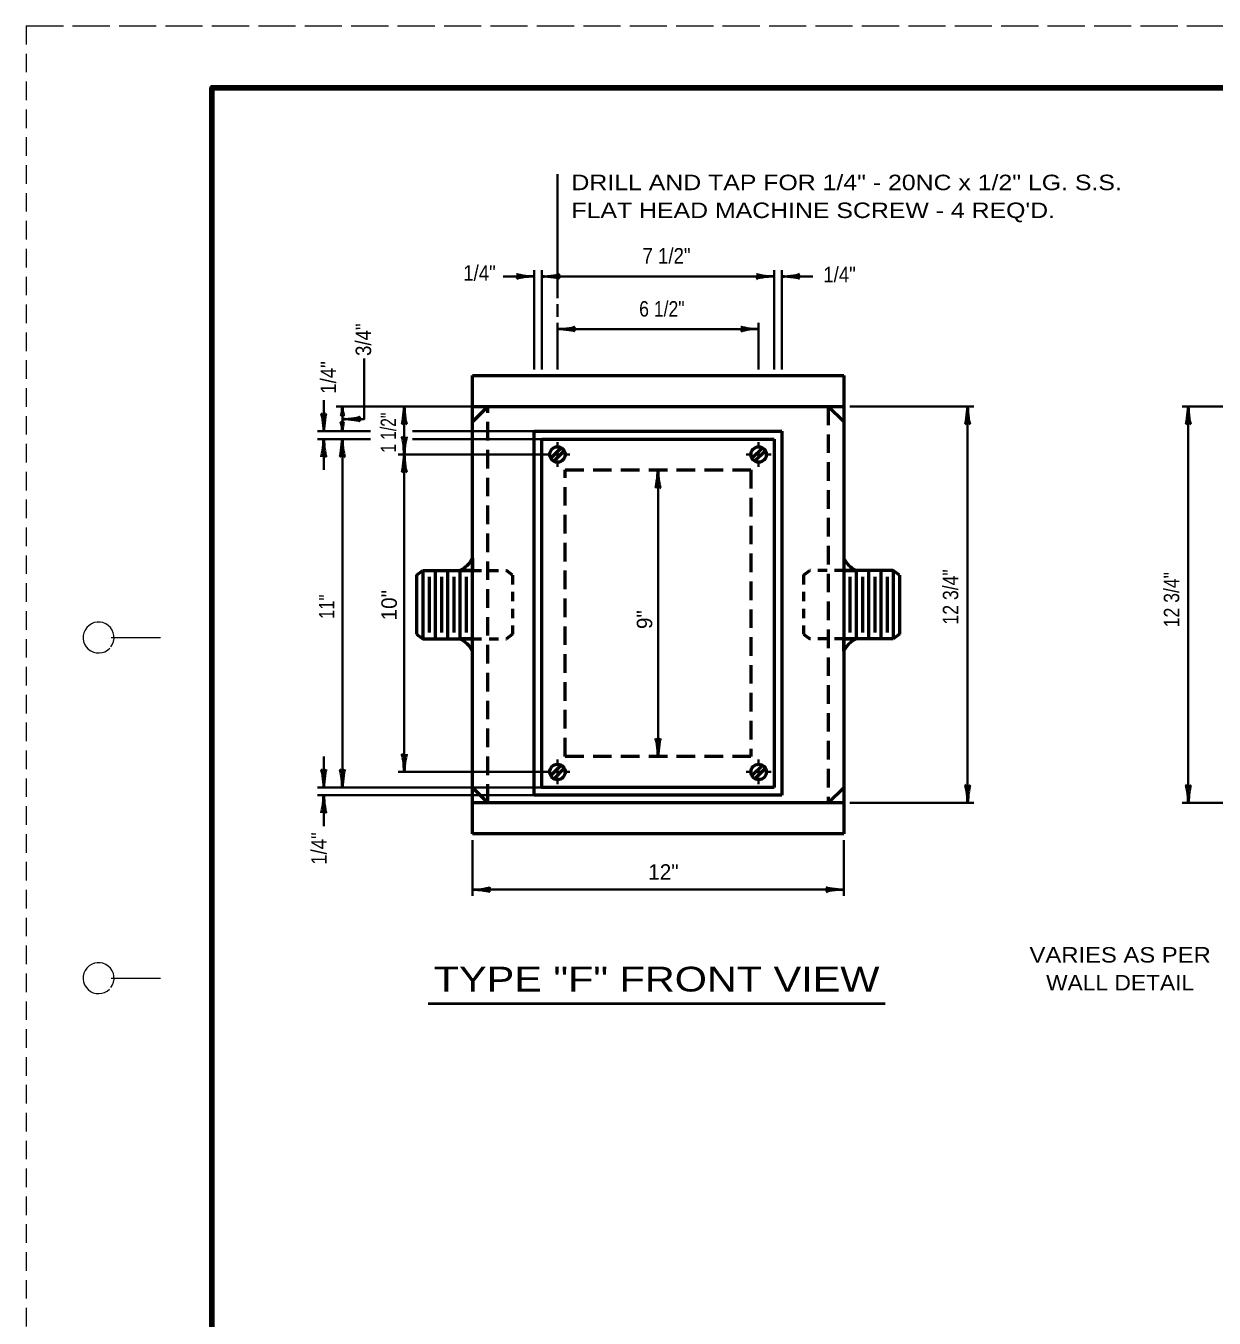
# Model space of a CAD drawing. Extents: x -1 to 679, y 0 to 440.
# Drawn here: x -1.4 to 190.5, y 231 to 439.6 of the extents above; entities that cross this region are included whole.
import ezdxf
from ezdxf.enums import TextEntityAlignment as Align

# ---------------------------------------------------------------- set-up
doc = ezdxf.new("R2010")
doc.units = 0
for name, pattern in [('LONG_DASHED', [7.5, 6, -1.5]), ('MEDIUM_DASHED', [4.5, 3, -1.5]), ('SHORT_DASHED', [2.7, 1.5, -1.2])]:
    doc.linetypes.add(name, pattern=pattern)
doc.layers.add('1', color=7, linetype='Continuous', lineweight=53)
doc.layers.add('61', color=7, linetype='Continuous', lineweight=35)

msp = doc.modelspace()

# ---------------------------------------------------------------- linework, layer by layer
at = {"layer": '1', "linetype": 'MEDIUM_DASHED', "lineweight": 13}
msp.add_line((-1.376, 439.629), (-1.436, -0.411), dxfattribs=at)
at = {"layer": '1', "lineweight": 35}
for p, q in [((84.441, 395.671), (84.441, 415.671)), ((80.691, 399.171), (75.691, 399.171)), ((80.691, 384.171), (80.691, 400.171)), ((81.941, 384.171), (81.941, 400.171)), ((81.941, 399.171), (119.441, 399.171)), ((119.441, 384.171), (119.441, 400.171)), ((120.691, 384.171), (120.691, 400.171)), ((120.691, 399.171), (125.691, 399.171)), ((84.441, 392.671), (84.441, 394.671)), ((84.441, 384.171), (84.441, 391.671)), ((84.441, 390.671), (116.941, 390.671)), ((116.941, 384.171), (116.941, 391.671)), ((46.691, 379.171), (46.691, 374.171)), ((70.691, 378.171), (48.691, 378.171)), ((49.691, 378.171), (49.691, 374.171)), ((131.691, 378.171), (151.691, 378.171)), ((150.691, 378.171), (150.691, 314.171)), ((206.337, 378.171), (185.337, 378.171)), ((186.337, 378.171), (186.337, 314.171)), ((54.251, 374.171), (45.691, 374.171)), ((80.691, 374.171), (61.002, 374.171)), ((54.251, 372.921), (45.691, 372.921)), ((46.691, 372.921), (46.691, 367.921)), ((49.691, 372.921), (49.691, 316.671)), ((81.941, 372.921), (61.002, 372.921)), ((84.441, 371.421), (84.441, 372.421)), ((116.941, 371.421), (116.941, 372.421)), ((82.441, 370.421), (58.691, 370.421)), ((83.441, 370.421), (82.441, 370.421)), ((83.941, 370.421), (84.941, 370.421)), ((84.441, 369.921), (84.441, 370.921)), ((84.441, 369.421), (84.441, 368.421)), ((85.441, 370.421), (86.441, 370.421)), ((115.941, 370.421), (114.941, 370.421)), ((116.441, 370.421), (117.441, 370.421)), ((116.941, 370.921), (116.941, 369.921)), ((116.941, 369.421), (116.941, 368.421)), ((117.941, 370.421), (118.941, 370.421)), ((100.691, 321.671), (100.691, 367.921)), ((46.691, 321.671), (46.691, 316.671)), ((84.441, 320.171), (84.441, 321.171)), ((84.441, 318.671), (84.441, 319.671)), ((116.941, 320.171), (116.941, 321.171)), ((116.941, 319.671), (116.941, 318.671)), ((82.441, 319.171), (58.691, 319.171)), ((83.441, 319.171), (82.441, 319.171)), ((84.941, 319.171), (83.941, 319.171)), ((84.441, 318.171), (84.441, 317.171)), ((85.441, 319.171), (86.441, 319.171)), ((115.941, 319.171), (114.941, 319.171)), ((116.441, 319.171), (117.441, 319.171)), ((116.941, 318.171), (116.941, 317.171)), ((117.941, 319.171), (118.941, 319.171)), ((81.941, 316.671), (45.691, 316.671)), ((80.691, 315.421), (45.691, 315.421)), ((46.691, 315.421), (46.691, 310.421)), ((131.691, 314.171), (151.691, 314.171)), ((207.337, 314.171), (185.337, 314.171)), ((70.691, 308.171), (70.691, 299.171)), ((130.691, 308.171), (130.691, 299.171)), ((70.691, 300.171), (130.691, 300.171))]:
    msp.add_line(p, q, dxfattribs=at)
at = {"layer": '1'}
for p, q in [((70.691, 383.171), (130.691, 383.171)), ((70.691, 378.171), (70.691, 383.171)), ((130.691, 383.171), (130.691, 378.171)), ((70.691, 378.171), (130.691, 378.171)), ((70.691, 351.676), (70.691, 378.171)), ((80.691, 315.421), (80.691, 374.171)), ((80.691, 374.171), (120.691, 374.171)), ((120.691, 374.171), (120.691, 315.421)), ((81.941, 372.921), (119.441, 372.921)), ((83.343, 369.823), (85.039, 371.519)), ((115.843, 369.823), (117.539, 371.519)), ((119.441, 372.921), (119.441, 316.671)), ((85.539, 371.019), (83.843, 369.323)), ((118.039, 371.019), (116.343, 369.323)), ((61.691, 350.921), (62.691, 351.671)), ((61.691, 350.921), (61.691, 341.421)), ((62.691, 351.671), (70.671, 351.671)), ((62.691, 351.671), (62.691, 340.671)), ((63.691, 350.671), (63.691, 341.671)), ((64.691, 351.671), (64.691, 340.671)), ((65.691, 350.671), (65.691, 341.671)), ((66.691, 351.671), (66.691, 340.671)), ((67.691, 350.671), (67.691, 341.671)), ((68.691, 351.671), (68.691, 340.671)), ((69.691, 350.671), (69.691, 341.671)), ((70.691, 316.671), (70.691, 351.671)), ((138.691, 351.671), (130.691, 351.671)), ((131.691, 350.671), (131.691, 341.671)), ((132.691, 351.671), (132.691, 340.671)), ((133.691, 350.671), (133.691, 341.671)), ((134.691, 351.671), (134.691, 340.671)), ((135.691, 350.671), (135.691, 341.671)), ((136.691, 351.671), (136.691, 340.671)), ((137.691, 350.671), (137.691, 341.671)), ((138.691, 351.671), (138.691, 340.671)), ((139.691, 350.921), (138.691, 351.671)), ((139.691, 350.921), (139.691, 341.421)), ((61.691, 341.421), (62.691, 340.671)), ((62.691, 340.671), (70.691, 340.671)), ((138.691, 340.671), (130.691, 340.671)), ((139.691, 341.421), (138.691, 340.671)), ((83.343, 318.573), (85.039, 320.269)), ((85.539, 319.769), (83.843, 318.073)), ((115.843, 318.573), (117.539, 320.269)), ((116.343, 318.073), (118.039, 319.769)), ((70.691, 309.171), (70.691, 316.671)), ((120.691, 315.421), (80.691, 315.421)), ((130.691, 314.171), (70.691, 314.171)), ((130.691, 309.171), (70.691, 309.171))]:
    msp.add_line(p, q, dxfattribs=at)
at = {"layer": '1', "linetype": 'MEDIUM_DASHED'}
for p, q in [((73.191, 314.171), (73.191, 378.171)), ((128.191, 378.171), (128.191, 314.171)), ((85.691, 321.671), (85.691, 367.921)), ((85.691, 367.921), (115.691, 367.921))]:
    msp.add_line(p, q, dxfattribs=at)
at = {"layer": '1', "linetype": 'SHORT_DASHED'}
for p, q in [((70.691, 351.671), (76.191, 351.671)), ((77.191, 350.921), (76.191, 351.671)), ((77.191, 350.921), (77.191, 341.421)), ((124.191, 350.921), (125.191, 351.671)), ((124.191, 350.921), (124.191, 341.421)), ((130.691, 351.671), (125.191, 351.671)), ((70.691, 340.671), (76.191, 340.671)), ((77.191, 341.421), (76.191, 340.671)), ((124.191, 341.421), (125.191, 340.671)), ((130.691, 340.671), (125.191, 340.671))]:
    msp.add_line(p, q, dxfattribs=at)
at = {"layer": '1', "lineweight": 40}
msp.add_line((63.568, 281.786), (137.369, 281.786), dxfattribs=at)
at = {"layer": '1', "lineweight": 35}
for points in [[(49.745, 376.133), (53.232, 376.133), (53.232, 385.936)], [(59.691, 378.171), (59.691, 370.421), (59.691, 319.171)]]:
    msp.add_lwpolyline(points, dxfattribs=at)
at = {"layer": '1'}
for points in [[(70.691, 378.171), (73.191, 378.171), (70.691, 375.671)], [(128.191, 378.171), (130.691, 378.171), (130.691, 375.671)], [(70.691, 314.171), (70.691, 316.671), (73.191, 314.171)], [(130.691, 314.171), (128.191, 314.171), (130.691, 316.671)]]:
    msp.add_lwpolyline(points, close=True, dxfattribs=at)
for points in [[(130.691, 378.171), (130.691, 316.671), (130.691, 309.171)], [(119.441, 316.671), (81.941, 316.671), (81.941, 372.921)], [(70.691, 353.671), (70.691, 351.671), (68.691, 351.671)], [(130.691, 353.671), (130.691, 351.671), (132.691, 351.671)], [(70.691, 338.671), (70.691, 340.671), (68.691, 340.671)], [(130.691, 338.671), (130.691, 340.671), (132.691, 340.671)]]:
    msp.add_lwpolyline(points, dxfattribs=at)
at = {"layer": '1', "linetype": 'MEDIUM_DASHED'}
msp.add_lwpolyline([(115.691, 367.921), (115.691, 321.671), (85.691, 321.671)], dxfattribs=at)
at = {"layer": '1'}
for centre in [(84.441, 370.421), (116.941, 370.421), (84.441, 319.171), (116.941, 319.171)]:
    msp.add_circle(centre, 1.25, dxfattribs=at)
for centre, start, end in [((66.811, 355.552), 295.85509, 334.14491), ((134.572, 355.552), 205.85509, 244.14491), ((66.811, 336.791), 25.85509, 64.14491), ((134.572, 336.791), 115.85509, 154.14491)]:
    msp.add_arc(centre, 4.312, start, end, dxfattribs=at)
at = {"layer": '1', "lineweight": 40}
for centre, major_axis, ratio, start_param, end_param in [((79.6, 398.895), (1.786, 0.156), 0.122415, 0.8963533, 3.1415927), ((79.571, 399.383), (1.756, -0.176), 0.07063, 3.1407148, 5.41811), ((83.032, 399.447), (-1.786, -0.156), 0.122415, 0.8963533, 3.1415927), ((83.032, 399.447), (-1.786, -0.156), 0.122415, 0.8963533, 3.1415927), ((83.062, 398.959), (-1.756, 0.176), 0.07063, 3.1407148, 5.41811), ((83.062, 398.959), (-1.756, 0.176), 0.07063, 3.1407148, 5.41811), ((118.35, 398.895), (1.786, 0.156), 0.122415, 0.8963533, 3.1415927), ((118.321, 399.383), (1.756, -0.176), 0.07063, 3.1407148, 5.41811), ((121.782, 399.447), (-1.786, -0.156), 0.122415, 0.8963533, 3.1415927), ((121.812, 398.959), (-1.756, 0.176), 0.07063, 3.1407148, 5.41811), ((85.532, 390.947), (-1.786, -0.156), 0.122415, 0.8963533, 3.1415927), ((85.562, 390.459), (-1.756, 0.176), 0.07063, 3.1407148, 5.41811), ((115.85, 390.395), (1.786, 0.156), 0.122415, 0.8963533, 3.1415927), ((115.85, 390.395), (1.786, 0.156), 0.122415, 0.8963533, 3.1415927), ((115.821, 390.883), (1.756, -0.176), 0.07063, 3.1407148, 5.41811), ((115.821, 390.883), (1.756, -0.176), 0.07063, 3.1407148, 5.41811), ((49.419, 377.439), (0.156, 1.786), 0.122415, 4.7072452, 5.1459979), ((49.955, 377.439), (-0.156, 1.786), 0.122415, 1.1378214, 1.5759401), ((59.479, 377.051), (0.176, 1.756), 0.07063, 3.1407148, 5.41811), ((59.967, 377.08), (-0.156, 1.786), 0.122415, 0.8963533, 3.1415927), ((150.479, 377.051), (0.176, 1.756), 0.07063, 3.1407148, 5.41811), ((150.479, 377.051), (0.176, 1.756), 0.07063, 3.1407148, 5.41811), ((150.967, 377.08), (-0.156, 1.786), 0.122415, 0.8963533, 3.1415927), ((150.967, 377.08), (-0.156, 1.786), 0.122415, 0.8963533, 3.1415927), ((186.126, 377.051), (0.176, 1.756), 0.07063, 3.1407148, 5.41811), ((186.126, 377.051), (0.176, 1.756), 0.07063, 3.1407148, 5.41811), ((186.613, 377.08), (-0.156, 1.786), 0.122415, 0.8963533, 3.1415927), ((186.613, 377.08), (-0.156, 1.786), 0.122415, 0.8963533, 3.1415927), ((46.415, 375.262), (0.156, -1.786), 0.122415, 0.8963533, 3.1415927), ((46.903, 375.292), (-0.176, -1.756), 0.07063, 3.1407148, 5.41811), ((49.553, 373.903), (0.156, -1.786), 0.122415, 2.1736985, 3.1415927), ((49.633, 378.41), (0.176, 1.756), 0.07063, 3.1407148, 4.1144709), ((50.866, 375.922), (-1.756, 0.176), 0.07063, 3.1407148, 5.41811), ((49.829, 378.439), (-0.156, 1.786), 0.122415, 2.1736985, 3.1415927), ((50.837, 376.41), (-1.786, -0.156), 0.122415, 0.8963533, 3.1415927), ((49.749, 373.932), (-0.176, -1.756), 0.07063, 3.1407148, 4.1144709), ((49.427, 374.903), (0.156, -1.786), 0.122415, 1.1378214, 1.5759401), ((49.964, 374.903), (-0.156, -1.786), 0.122415, 4.7072452, 5.1459979), ((46.479, 371.801), (0.176, 1.756), 0.07063, 3.1407148, 5.41811), ((46.967, 371.83), (-0.156, 1.786), 0.122415, 0.8963533, 3.1415927), ((49.479, 371.801), (0.176, 1.756), 0.07063, 3.1407148, 5.41811), ((49.967, 371.83), (-0.156, 1.786), 0.122415, 0.8963533, 3.1415927), ((59.415, 371.512), (0.156, -1.786), 0.122415, 0.8963533, 3.1415927), ((59.903, 371.542), (-0.176, -1.756), 0.07063, 3.1407148, 5.41811), ((59.479, 369.301), (0.176, 1.756), 0.07063, 3.1407148, 5.41811), ((59.967, 369.33), (-0.156, 1.786), 0.122415, 0.8963533, 3.1415927), ((100.479, 366.801), (0.176, 1.756), 0.07063, 3.1407148, 5.41811), ((100.479, 366.801), (0.176, 1.756), 0.07063, 3.1407148, 5.41811), ((100.967, 366.83), (-0.156, 1.786), 0.122415, 0.8963533, 3.1415927), ((100.967, 366.83), (-0.156, 1.786), 0.122415, 0.8963533, 3.1415927), ((100.415, 322.762), (0.156, -1.786), 0.122415, 0.8963533, 3.1415927), ((100.903, 322.792), (-0.176, -1.756), 0.07063, 3.1407148, 5.41811), ((59.415, 320.262), (0.156, -1.786), 0.122415, 0.8963533, 3.1415927), ((59.903, 320.292), (-0.176, -1.756), 0.07063, 3.1407148, 5.41811), ((46.415, 317.762), (0.156, -1.786), 0.122415, 0.8963533, 3.1415927), ((46.903, 317.792), (-0.176, -1.756), 0.07063, 3.1407148, 5.41811), ((49.415, 317.762), (0.156, -1.786), 0.122415, 0.8963533, 3.1415927), ((49.903, 317.792), (-0.176, -1.756), 0.07063, 3.1407148, 5.41811), ((46.479, 314.301), (0.176, 1.756), 0.07063, 3.1407148, 5.41811), ((46.967, 314.33), (-0.156, 1.786), 0.122415, 0.8963533, 3.1415927), ((150.415, 315.262), (0.156, -1.786), 0.122415, 0.8963533, 3.1415927), ((150.415, 315.262), (0.156, -1.786), 0.122415, 0.8963533, 3.1415927), ((150.903, 315.292), (-0.176, -1.756), 0.07063, 3.1407148, 5.41811), ((150.903, 315.292), (-0.176, -1.756), 0.07063, 3.1407148, 5.41811), ((186.061, 315.262), (0.156, -1.786), 0.122415, 0.8963533, 3.1415927), ((186.549, 315.292), (-0.176, -1.756), 0.07063, 3.1407148, 5.41811), ((71.782, 300.447), (-1.786, -0.156), 0.122415, 0.8963533, 3.1415927), ((71.782, 300.447), (-1.786, -0.156), 0.122415, 0.8963533, 3.1415927), ((129.571, 300.383), (1.756, -0.176), 0.07063, 3.1407148, 5.41811), ((71.812, 299.959), (-1.756, 0.176), 0.07063, 3.1407148, 5.41811), ((71.812, 299.959), (-1.756, 0.176), 0.07063, 3.1407148, 5.41811), ((129.6, 299.895), (1.786, 0.156), 0.122415, 0.8963533, 3.1415927)]:
    msp.add_ellipse(centre, major_axis=major_axis, ratio=ratio, start_param=start_param, end_param=end_param, dxfattribs=at)
at = {"layer": '61', "linetype": 'LONG_DASHED', "lineweight": 13}
msp.add_line((-1.376, 439.629), (678.644, 439.629), dxfattribs=at)
at = {"layer": '61', "lineweight": 13}
for p, q in [((12.344, 340.869), (20.324, 340.889)), ((12.324, 285.869), (20.324, 285.869))]:
    msp.add_line(p, q, dxfattribs=at)
at = {"layer": '61', "lineweight": 158}
msp.add_lwpolyline([(667.664, 429.629), (28.624, 429.629), (28.624, 9.609)], dxfattribs=at)
at = {"layer": '61', "lineweight": 13}
for centre, end in [((10.321, 340.871), 316.23216), ((10.321, 285.871), 315.37577)]:
    msp.add_arc(centre, 2.5, 323.13009, end, dxfattribs=at)

# ---------------------------------------------------------------- texts
at = {"layer": '1', "width": 1.2}
for s, p in [('DRILL AND TAP FOR 1/4" - 20NC x 1/2" LG. S.S.', (86.699, 413.098)), ("FLAT HEAD MACHINE SCREW - 4 REQ'D.", (86.699, 408.598))]:
    msp.add_text(s, height=2.5, dxfattribs=at).set_placement(p)
at = {"layer": '1'}
for s, height, width, p in [('7 1/2"', 2.5, 0.9, (102.057, 401.251)), ('1/4"', 2.5, 0.9, (71.844, 398.481)), ('1/4"', 2.5, 0.9, (130.004, 398.229)), ('6 1/2"', 2.5, 0.85, (101.302, 392.688)), ('VARIES AS PER', 2.5, 1.15, (175.33, 288.393)), ('TYPE "F" FRONT VIEW', 4, 1.25, (100.451, 283.719)), ('WALL DETAIL', 2.5, 1.1, (175.33, 283.893))]:
    msp.add_text(s, height=height, dxfattribs=dict(at, width=width)).set_placement(p, align=Align.CENTER)
for s, width, p in [('3/4"', 0.9, (54.337, 388.959)), ('1/4"', 0.9, (48.671, 382.856)), ('1 1/2"', 0.75, (58.379, 373.95)), ('12 3/4"', 0.85, (149.182, 347.423)), ('12 3/4"', 0.85, (184.88, 346.981)), ('11"', 0.8, (48.42, 345.833)), ('1/4"', 0.9, (47.161, 306.795))]:
    msp.add_text(s, height=2.5, rotation=90, dxfattribs=dict(at, width=width)).set_placement(p, align=Align.CENTER)
for s, p in [('10"', (58.491, 346.085)), ('9"', (99.754, 343.76))]:
    msp.add_text(s, height=2.5, rotation=90, dxfattribs=at).set_placement(p, align=Align.CENTER)
msp.add_text('12"', height=2.5, dxfattribs=at).set_placement((101.553, 301.767), align=Align.CENTER)

doc.saveas('drawing.dxf')
